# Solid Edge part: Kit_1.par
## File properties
Sűrűség: 0,000 kg/m^3
Pontosság: 0,990
Author: ahadarics
Last saved by: psaghy
Revision: 78
Username: ahadarics
Dokumentum tartalom típus: 0
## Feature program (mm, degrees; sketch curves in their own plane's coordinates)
base feature "unnamed BaseFeature 1"
sketch for "Furat_1" plane through (0, 0, 41.5) normal (0, 0, 1) x-axis (-0.707107, -0.707107, 0)
  hole centre (-39.9515, 0) bore radius 3.3235
hole "Furat_1" nominal diameter 8 finite  VBottomAngle = 118 deg
sketch for "unnamed Hole 1" plane through (0, 0, 41.5) normal (0, 0, 1) x-axis (-0.707107, -0.707107, 0)
  hole centre (0, 39.9515) bore radius 3.3235
hole "unnamed Hole 1" finite
sketch for "unnamed Hole 2" plane through (0, 0, 41.5) normal (0, 0, 1) x-axis (-0.707107, -0.707107, 0)
  hole centre (39.9515, 0) bore radius 3.3235
hole "unnamed Hole 2" finite
sketch for "unnamed Hole 3" plane through (0, 0, 41.5) normal (0, 0, 1) x-axis (-0.707107, -0.707107, 0)
  hole centre (0, -39.9515) bore radius 3.3235
hole "unnamed Hole 3" finite
pattern "unnamed Pattern 1" of "Furat_1", "unnamed Hole 1", "unnamed Hole 2", "unnamed Hole 3"
sketch for "Furat_5" plane through (37.5, 0.0062, 22.7488) normal (1, 0, 0) x-axis (0, 0, 1)
hole "Furat_5" diameter 16.662 finite  ThreadDepth = 17 mm
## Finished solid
Body 1: solid body, 484 faces, 1114 edges, 686 vertices, 7 internal voids.
  Faces by surface: cylinder 197, plane 138, torus 42, cone 39, sphere 37, spline 27, swept 4
  Edges by curve: curve on surface 472, circle 322, line 309, spline 11
Bounding box of the edges (mm; curved faces can reach further): 75.001 x 75.000 x 37.500, from (-37.5, -37.5, 8) to (37.5009, 37.5, 45.5).
Cylindrical faces by radius (mm): R0.3049 x1, R0.3063 x2, R0.3073 x1, R0.3094 x1, R0.3138 x1, R0.3275 x1, R0.3358 x1, R0.3579 x2, R0.3595 x2, R0.3746 x2, R0.3825 x2, R0.3862 x2, R0.3932 x1, R0.395 x1, R0.3966 x1, R0.3998 x2, R0.4022 x1, R0.4063 x1, R0.4065 x1, R0.4073 x2, R0.4133 x1, R0.4335 x2, R0.4417 x1, R0.4627 x2, R0.4813 x1, R0.4994 x1, R0.5 x3, R0.5003 x1, R0.5051 x1, R0.5233 x1, R0.5325 x1, R0.5327 x1, R0.5437 x2, R0.5682 x1, R0.5785 x2, R0.6044 x1, R0.6048 x2, R0.6079 x1, R0.6085 x1, R0.6126 x1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
Conical faces (half-angle, radius in mm at the cone's reference point): 1 deg R23.75 x4, 1 deg R28 x4, 30 deg R5.1443 x1, 32.8285 deg R32.5 x1, 37.7468 deg R27.2199 x3, 37.7468 deg R33.5 x3, 45 deg R2.75 x1, 45 deg R2.825 x1, 45 deg R4.3 x8, 45 deg R6.35 x8, 45 deg R7.47 x1, 59 deg R3.3235 x4
Toroidal faces (ring radius, tube radius in mm): R0.5012 r0.5005 x1, R1 r0.5 x1, R1.0357 r0.4999 x1, R4.3 r0.3 x4, R4.7 r0.3 x1, R6.45 r0.2 x4, R7.15 r0.5 x4, R10.25 r1 x2, R12 r0.5 x1, R22 r0.5 x1, R23 r0.5 x1, R24.6454 r1 x1, R24.7327 r1 x3, R25.9494 r1 x3, R27.0059 r1 x3, R27.0694 r1 x1, R34 r1 x3, R38.0449 r1 x1, R38.5 r1 x6
Spherical faces by radius (mm): R1 x37
Planar faces by outward normal: +x 22, +y 8, +z 25, -x 2, -y 7, -z 16, oblique 58
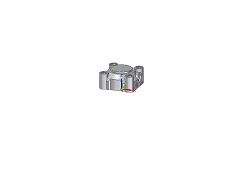
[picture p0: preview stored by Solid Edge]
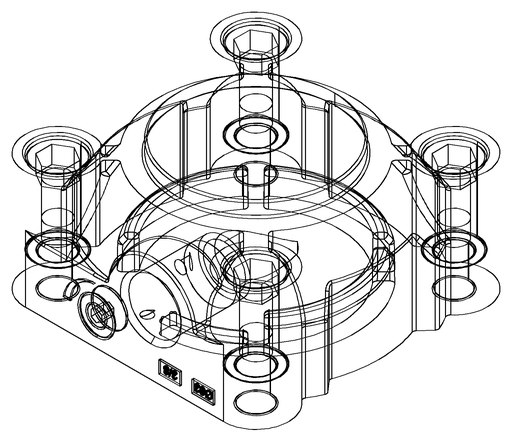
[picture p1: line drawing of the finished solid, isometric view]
